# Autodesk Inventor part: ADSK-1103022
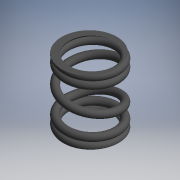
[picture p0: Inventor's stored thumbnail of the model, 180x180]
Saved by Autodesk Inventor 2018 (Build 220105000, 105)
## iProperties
Shininess: 24.0
Length Units: 11272
Angle Units: 11279
Time Units: 11290
Mass Units: 11286
Length Display Precision: 4
Angle Display Precision: 2
Compacted: True
Created: 2000-03
Part Number: ADSK-1103022
Document SubType Name: Modeling
Description: UHAN SPRING #334-2
Mass: 0.0822308 g
Surface Area: 0.886826 cm^2
Volume: 0.0101771 cm^3
Density: 8.08 g/cm^3
Material: Stainless Steel
Appearance: Black
Density: 0.0
Volumn: 0.0
Area: 0.0
PropertySet Name: Model Information
Control State: 0
Master: False
Checked Out: False
Author: Autodesk, Inc.
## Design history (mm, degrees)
sketch "Sketch2"
  geometry: L1 (-14.979, -10.854)-(-14.979, 14.546); A1 r 0.254 centre (-16.757, -11.108) between (-16.503, -11.108) and (-16.757, -10.854); 1 further point
  constraints: 2 end point, 2 horizontal alignment, 2 point on circle, 2 vertical alignment, 1 centre point, 1 vertical, 5 other
  dimensions: "d0" = 25.4 distance of L1.start L1.end; "d1" = 3.048 diameter of A1.start L1; "d2" = 0.508 diameter of A1
node "Coil1" dims "d3" = 3.175 (= 0.125 x d0), "d4" = 2.921, "d5" = 12.5, "d6" = 0, "d7" = 30 deg, "d8" = 1 deg, "d9" = 30 deg, "d10" = 1 deg
workaxis "Work Axis1"
node "Coil2" dims "d11" = 0.5334 (computed from d2), "d12" = 25.4, "d13" = 20, "d14" = 0, "d15" = 90 deg, "d16" = 90 deg, "d17" = 0, "d18" = 0
  sketch "Sketch3"
    geometry: L1 (1.778, -1.011)-(1.778, 3.933) reference; C1 r 0.254 at (0, 0) reference
node "Extrusion1" dims "d19" = 25.4, "d20" = 0
  sketch "Sketch4"
    geometry: L1 (-2.213, -5.897)-(17.486, -5.897); L2 (17.486, -5.897)-(17.486, 0.254); L3 (17.486, 0.254)-(-2.213, 0.254); L4 (-2.213, 0.254)-(-2.213, -5.897); C1 r 0.254 at (0, 0) reference
    constraints: 8 end point, 2 parallel, 1 horizontal, 1 perpendicular, 1 tangent
node "Coil3" dims "d21" = 0.5334 (computed from d2), "d22" = 25.4, "d23" = 20, "d24" = 0, "d25" = 90 deg, "d26" = 90 deg, "d27" = 0, "d28" = 0
  sketch "Sketch5"
    geometry: L1 (-1.778, -3.932)-(-1.778, 1.012) reference; C1 r 0.254 at (0, 0) reference
node "Extrusion2" dims "d29" = 25.4, "d30" = 0
  sketch "Sketch6"
    geometry: L1 (7.067, 10.875)-(-19.265, 10.875); L2 (-19.265, 10.875)-(-19.265, -0.254); L3 (-19.265, -0.254)-(7.067, -0.254); L4 (7.067, -0.254)-(7.067, 10.875); C1 r 0.254 at (0, 0) reference
    constraints: 8 end point, 2 parallel, 1 horizontal, 1 perpendicular, 1 tangent
body "Solid1"
